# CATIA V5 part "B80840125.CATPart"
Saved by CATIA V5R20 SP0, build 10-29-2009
Part number: B80840125
Revision: 3
Definition: design
Nomenclature: B80840125
Source: made
Description: NOT SPECIFIED
Bounding box of the stored display mesh (mm): x -22.5 to 22.5, y -22.5 to 22.5, z 0 to 125
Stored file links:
  C:\Users\Raffaele\Desktop\3D X SITO CF\BOLEX\4-PILLAR REF 808\B80840125.CATPart
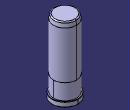
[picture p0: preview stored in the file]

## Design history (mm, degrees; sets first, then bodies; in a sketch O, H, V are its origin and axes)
Body1 "MANIFOLD_SOLID_BREP #450" (main body)
  Solid1: solid without history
